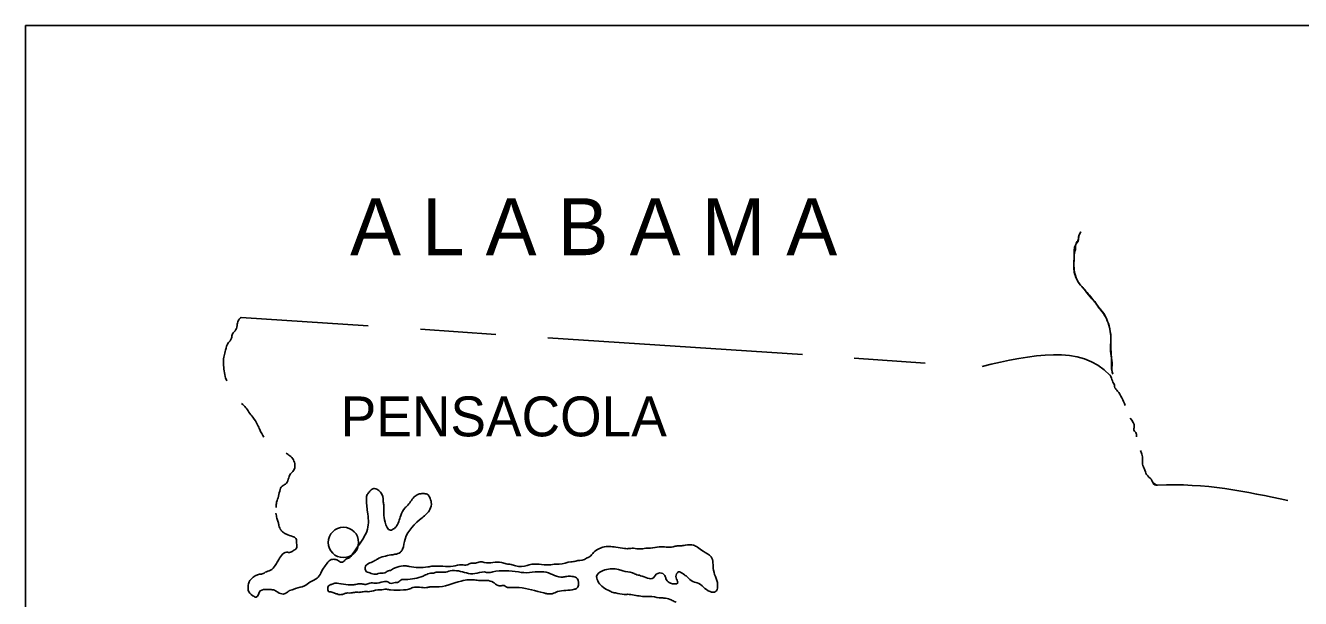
# Model space of a CAD drawing. Extents: x 315926 to 491925, y 1158891 to 1294891.
# Drawn here: x 435411 to 448942, y 1280810 to 1286891 of the extents above; entities that cross this region are included whole.
import ezdxf

# ---------------------------------------------------------------- set-up
doc = ezdxf.new("R2010")
doc.units = 0
doc.layers.add('V-ANNO-SYMB', color=7, linetype='Continuous')

msp = doc.modelspace()

# ---------------------------------------------------------------- linework, layer by layer
at = {"layer": 'V-ANNO-SYMB'}
for p, q in [((474924.24152864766, 1286890.60258966), (435411.05736746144, 1286890.5877054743)), ((435411.0573680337, 1286890.5877054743), (435411.0573726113, 1251238.69202066)), ((439048.86632875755, 1283701.8936220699), (437699.54312891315, 1283792.332821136)), ((440403.2367284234, 1283611.4328222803), (439602.3375285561, 1283666.570421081)), ((443655.95192865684, 1283399.299222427), (440953.12232889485, 1283576.044822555)), ((444958.84952825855, 1283307.4056223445), (444206.2263289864, 1283361.981621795))]:
    msp.add_line(p, q, dxfattribs=at)
msp.add_circle((438785.0007281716, 1281404.568021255), 160.9968943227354, dxfattribs=at)
msp.add_arc((447465.82008299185, 1282126.484151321), 121.89745971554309, 213.18290550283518, 248.6293777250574, dxfattribs=at)
for points in [[(446948.72072920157, 1283194.1496222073), (446937.812727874, 1283248.7328222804), (446937.812727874, 1283344.2408224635), (446929.6335290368, 1283453.3928225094), (446929.6335284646, 1283578.917622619), (446910.5607284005, 1283703.5424215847), (446875.10792879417, 1283793.6000231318), (446823.29672865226, 1283870.006421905), (446749.66952871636, 1283968.2432222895), (446651.5047282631, 1284085.5816217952), (446575.14872812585, 1284181.0896219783), (446537.0895286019, 1284303.2952234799), (446539.8183288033, 1284450.650422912), (446553.4551286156, 1284559.802422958), (446586.1719285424, 1284617.1144220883), (446586.1719285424, 1284647.1312231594), (446613.445528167, 1284701.7072214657)], [(446949.9015283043, 1283190.1680223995), (446942.70152887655, 1283211.7680223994), (446942.7015283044, 1283308.9680223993), (446928.30152830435, 1283409.7680223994), (446928.30152830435, 1283596.968023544), (446913.90152887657, 1283686.9680223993), (446881.50152830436, 1283780.5680223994), (446823.90152887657, 1283874.1680223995), (446802.30152887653, 1283895.768021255), (446759.1015288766, 1283960.5680223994), (446708.70152887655, 1284010.9680223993), (446643.90152887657, 1284097.3680223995), (446597.1015288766, 1284147.7680223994), (446553.90152944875, 1284237.7680223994), (446539.50152830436, 1284316.9680223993), (446539.50152887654, 1284424.968023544), (446546.70152887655, 1284489.7680223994), (446553.9015283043, 1284514.9680223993), (446561.10152830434, 1284579.7680223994), (446582.70152773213, 1284615.7680223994), (446589.9015283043, 1284658.9680223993), (446611.5015277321, 1284702.1680223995)], [(437699.54312891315, 1283792.332821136), (437674.1055289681, 1283767.6728220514), (437658.3591287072, 1283720.4120211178), (437642.61992906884, 1283663.3088205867), (437609.161527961, 1283618.0136202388), (437597.36072840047, 1283572.7256205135), (437581.6143281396, 1283543.1840204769), (437565.8751285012, 1283527.4304201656), (437534.3895286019, 1283444.7240213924), (437518.64312834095, 1283385.6480219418), (437510.7735288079, 1283322.6336206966), (437516.6775283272, 1283243.865621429), (437530.4511285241, 1283167.0632204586), (437538.32072862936, 1283139.494420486), (437548.1631287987, 1283119.802420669)], [(447081.8271291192, 1282858.809622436), (447000.0207286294, 1283011.6224234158), (446983.65512918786, 1283030.7240213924), (446972.7471284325, 1283047.0968226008), (446967.29672865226, 1283074.39202066), (446945.48072885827, 1283118.0528215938), (446920.93592886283, 1283178.0864225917), (446918.52392858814, 1283180.7360228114), (445562.1231284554, 1283273.2200235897)], [(437703.56792787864, 1282879.09202066), (437750.799928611, 1282833.8040209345), (437780.312727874, 1282788.5088205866), (437823.60632910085, 1282733.3712206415), (437874.76952871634, 1282652.637620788), (437896.4199290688, 1282601.4384226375), (437941.67912916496, 1282520.6976221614)], [(447201.6783290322, 1282526.7528227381), (447198.9495282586, 1282562.2272219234), (447174.4119294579, 1282594.9800226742), (447177.1335284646, 1282630.4544230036), (447133.5087294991, 1282723.2336229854)], [(438177.39992861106, 1282352.109622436), (438216.75512861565, 1282324.5408213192), (438254.1447291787, 1282281.2184221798), (438269.8911288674, 1282226.0808210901), (438256.1175286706, 1282167.0048227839), (438224.63192877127, 1282133.524820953), (438169.53032907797, 1282023.2496210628), (438136.0791291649, 1282003.557621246), (438108.5319293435, 1281950.3856207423), (438090.8199284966, 1281877.5288210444), (438073.10792936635, 1281818.4528215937), (438071.1423282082, 1281777.0960207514)], [(448806.7599288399, 1281848.7504217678), (447425.08712877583, 1282012.2552225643), (447395.084729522, 1282014.9840227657), (447365.0895286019, 1282061.3736227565), (447321.46472906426, 1282110.4920229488), (447299.6487292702, 1282140.5088217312), (447291.46232809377, 1282170.5256228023), (447269.6535283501, 1282219.64402185), (447266.9247287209, 1282282.4064241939), (447258.7455293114, 1282342.4400217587), (447242.3799287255, 1282380.6432222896)], [(438068.70152887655, 1281714.1680223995), (438079.50152887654, 1281663.768021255), (438093.9015283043, 1281620.5680223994), (438101.1015288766, 1281584.5680201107), (438122.7015283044, 1281534.1680223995), (438144.30152944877, 1281512.568021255), (438180.30152944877, 1281490.9680223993), (438245.10153002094, 1281469.3680212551), (438281.10152944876, 1281447.7680223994), (438288.30152887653, 1281397.3680212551), (438288.30152887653, 1281343.3680212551), (438259.50152887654, 1281321.7680201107), (438223.50152830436, 1281300.168021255), (438180.30152887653, 1281300.1680201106), (438090.30152887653, 1281206.5680223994), (438061.50152887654, 1281159.7680223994), (438011.10152944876, 1281109.3680223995), (437953.50152887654, 1281087.7680201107), (437931.90152887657, 1281073.3680212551), (437895.90152887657, 1281066.1680201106), (437809.50153002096, 1281019.3680201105), (437780.70152887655, 1280976.1680223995), (437773.50152887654, 1280925.7680223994), (437773.50152887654, 1280896.9680201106), (437823.90152944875, 1280839.3680201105), (437859.90152944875, 1280824.968021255), (437903.10153002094, 1280889.7680201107), (437975.1015288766, 1280904.1680201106), (438003.90152887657, 1280904.1680201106), (438054.30152887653, 1280896.9680223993), (438090.30152887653, 1280875.3680212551), (438147.90152887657, 1280857.3680212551), (438183.90152887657, 1280871.7680223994), (438212.70152887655, 1280893.3680201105), (438241.50152887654, 1280900.5680223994), (438277.50152887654, 1280914.968021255), (438371.10152944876, 1280943.768021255), (438428.70152887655, 1280983.3680201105), (438507.90152944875, 1281026.5680201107), (438543.90152887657, 1281076.968021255), (438565.5015294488, 1281120.1680201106), (438601.5015294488, 1281170.568021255), (438644.70152887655, 1281217.3680201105), (438695.1015288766, 1281224.568021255), (438731.1015288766, 1281210.1680223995), (438752.70152887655, 1281195.7680223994), (438795.90152944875, 1281210.1680223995), (438817.50152887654, 1281231.768021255), (438839.1015288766, 1281238.9680223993), (438882.30152944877, 1281282.1680223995), (438997.50152887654, 1281451.3680212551), (439040.70152944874, 1281544.968021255), (439040.70152887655, 1281728.568021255), (439029.90152944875, 1281872.5680223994), (439037.10152830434, 1281912.1680201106), (439065.90152887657, 1281948.168021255), (439080.30152887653, 1281962.5680223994), (439116.30152944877, 1281976.9680223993), (439159.50152887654, 1281955.3680212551), (439206.30152830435, 1281868.9680201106), (439206.30152944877, 1281847.3680212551), (439213.50152887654, 1281804.168021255), (439213.50153002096, 1281714.168021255), (439227.90152887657, 1281620.5680223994), (439285.50152887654, 1281534.168021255), (439307.10152944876, 1281541.3680201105), (439343.1015288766, 1281570.1680223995), (439393.50152887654, 1281688.968021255), (439436.70152887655, 1281768.168021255), (439458.30152887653, 1281789.768021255), (439537.50152830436, 1281886.9680223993), (439580.70152887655, 1281915.768021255), (439631.1015288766, 1281922.968021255), (439674.30152830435, 1281915.768021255), (439710.30152830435, 1281858.168021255), (439717.5015294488, 1281829.3680223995), (439703.1015288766, 1281753.768021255), (439620.30152887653, 1281667.3680223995), (439440.30152944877, 1281440.568021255), (439411.5015294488, 1281332.568021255), (439389.90152887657, 1281300.168021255), (439332.30152944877, 1281278.5680201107), (439289.1015288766, 1281271.3680212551), (439145.10152944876, 1281228.168021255), (439109.10152944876, 1281206.5680223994), (439015.50152887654, 1281138.1680223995), (439022.70152944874, 1281102.168021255), (439065.90152944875, 1281080.5680223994), (439123.50152887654, 1281066.168021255), (439152.30152887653, 1281073.3680212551), (439224.30152887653, 1281080.568021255)], [(439224.30152887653, 1281080.568021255), (439253.1015288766, 1281098.5680223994), (439296.30152944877, 1281112.9680223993), (439317.90152887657, 1281127.3680212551), (439353.90152887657, 1281141.7680223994), (439440.30152887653, 1281156.1680223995), (439483.5015294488, 1281148.968021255), (439681.50152887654, 1281145.3680223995), (439731.90152944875, 1281152.5680223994), (439947.90152887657, 1281152.568021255), (440041.50152887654, 1281166.9680201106), (440099.1015288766, 1281166.9680223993), (440142.30152944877, 1281184.9680223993), (440185.5015294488, 1281184.9680223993), (440235.90152944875, 1281199.3680201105), (440279.10152830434, 1281192.1680223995), (440462.70152944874, 1281192.1680223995), (440513.10152830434, 1281177.7680223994), (440563.50152830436, 1281170.568021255), (440613.90152944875, 1281156.1680223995), (440736.30152944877, 1281159.7680223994), (440757.90152944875, 1281166.968021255), (440966.70152887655, 1281166.968021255), (441038.70152944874, 1281174.1680223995), (441074.70152944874, 1281174.1680201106), (441200.701530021, 1281199.3680223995), (441251.10152944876, 1281206.5680223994), (441272.70152887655, 1281213.7680223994), (441294.30152830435, 1281213.7680223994), (441387.90152887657, 1281249.7680223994), (441409.50152830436, 1281264.168021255), (441438.30152830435, 1281296.5680223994), (441488.70152887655, 1281332.5680223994), (441539.1015288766, 1281354.1680223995), (441675.90152887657, 1281354.1680223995), (441769.50152887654, 1281339.7680201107), (441819.90152887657, 1281339.7680223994), (441848.7015283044, 1281343.3680223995), (441913.50152830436, 1281336.168021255), (441949.50152887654, 1281336.168021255), (442007.10152944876, 1281343.3680223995), (442043.1015288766, 1281343.3680212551), (442136.70152887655, 1281357.7680223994), (442284.30152944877, 1281357.7680223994), (442327.50152830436, 1281368.5680223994), (442363.50152887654, 1281368.5680223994), (442413.90152887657, 1281375.7680223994), (442500.30152887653, 1281375.768021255), (442543.5015294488, 1281354.168021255), (442601.1015288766, 1281310.9680223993), (442687.50152887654, 1281253.3680223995), (442712.70152887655, 1281109.3680212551), (442755.90152887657, 1280932.968021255), (442734.30152944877, 1280882.5680223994), (442676.70152887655, 1280882.5680223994), (442539.90152887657, 1280976.1680223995), (442511.10152944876, 1280983.3680223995), (442446.30152887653, 1281026.5680223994), (442431.9015283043, 1281040.9680223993), (442392.30152887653, 1281069.768021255), (442341.90152887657, 1281091.3680223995), (442320.30152887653, 1281069.768021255), (442320.30152944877, 1281015.768021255), (442331.10152944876, 1280972.5680223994), (442302.30152944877, 1280965.3680223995), (442255.5015294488, 1280972.5680223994), (442212.30152887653, 1281008.568021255), (442205.1015288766, 1281030.1680223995), (442176.30152887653, 1281073.3680212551), (442104.30152944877, 1281066.168021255), (442075.5015294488, 1281030.1680223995), (441938.70152944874, 1281051.7680223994), (441888.30152830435, 1281066.1680223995), (441852.30152887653, 1281080.5680223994), (441751.50153002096, 1281102.1680223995), (441704.70152944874, 1281116.5680223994), (441560.70152944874, 1281112.968021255), (441474.30152887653, 1281055.3680223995), (441528.30152887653, 1280940.1680223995), (441593.1015288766, 1280896.9680201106), (441621.901530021, 1280882.568021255), (441672.30152887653, 1280868.1680223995), (441765.90152944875, 1280853.7680223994), (441816.30152887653, 1280853.7680223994), (441960.30152944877, 1280832.1680223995), (442032.30152944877, 1280832.1680223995), (442136.70152887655, 1280817.7680223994), (442187.10152944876, 1280814.1680223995), (442251.90152887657, 1280799.7680223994), (442295.10152944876, 1280778.1680223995), (442316.70152887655, 1280770.9680201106)], [(438734.70152887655, 1280968.9680201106), (438835.50152887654, 1280954.5680223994), (438885.90152944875, 1280954.568021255), (438929.1015288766, 1280961.7680201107), (438979.50152887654, 1280965.3680212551), (439022.70152887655, 1280958.168021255), (439065.90152944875, 1280972.568021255), (439123.5015294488, 1280972.5680223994), (439206.30152944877, 1280986.968021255), (439256.7015283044, 1280986.968021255), (439278.30152887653, 1280972.568021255), (439307.10152830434, 1280972.5680223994), (439335.90152887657, 1280979.7680223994), (439357.50152887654, 1280979.7680201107), (439393.50152887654, 1281004.9680201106), (439443.90152887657, 1281012.1680201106), (439631.10152944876, 1281048.1680223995), (439681.50152887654, 1281069.7680223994), (439710.30152887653, 1281076.9680223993), (439731.90152887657, 1281076.9680201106), (439767.90152887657, 1281087.7680223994), (439854.30152830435, 1281087.768021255), (439919.1015288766, 1281102.168021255), (440005.50152830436, 1281102.1680223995), (440178.30152944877, 1281073.3680223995), (440282.70152887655, 1281091.3680223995), (440325.90152887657, 1281084.1680223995), (440369.1015288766, 1281091.3680223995), (440642.70152887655, 1281091.3680212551), (440700.30152887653, 1281084.1680201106), (440937.90152944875, 1281087.7680223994), (441114.30152887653, 1281037.3680201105), (441157.50152887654, 1281044.5680223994), (441207.90152887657, 1281044.5680223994), (441258.30152887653, 1281030.1680223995), (441279.90152944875, 1280965.3680223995), (441265.50152887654, 1280922.1680223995), (441236.70152887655, 1280907.7680223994), (441056.70152944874, 1280882.5680223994), (440999.10152944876, 1280860.9680223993), (440948.70152944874, 1280860.968021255), (440912.70152944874, 1280868.1680223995), (440649.90152887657, 1280925.7680223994), (440570.70152887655, 1280925.7680223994), (440513.10152830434, 1280932.9680223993), (440491.50152887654, 1280947.3680223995), (440448.30152830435, 1280943.768021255), (440405.10152944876, 1280958.1680223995), (440376.30152887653, 1280979.7680223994), (440304.30152944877, 1281001.3680223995), (440217.9015283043, 1281001.3680223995), (440160.30152887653, 1281008.5680223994), (440117.1015288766, 1281008.5680223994), (440034.30152887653, 1280994.1680223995), (439767.90152887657, 1280932.968021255), (439703.10152944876, 1280932.9680223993), (439667.1015288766, 1280925.768021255), (439523.10152944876, 1280925.7680201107), (439479.90152887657, 1280907.768021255), (439422.30152944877, 1280900.5680223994), (439285.50152887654, 1280900.568021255), (439242.30152887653, 1280907.768021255), (439177.50152887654, 1280900.5680223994), (439148.70152944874, 1280900.568021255), (439062.30152944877, 1280882.568021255), (439008.30152887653, 1280882.5680201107), (438957.90152944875, 1280875.3680201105), (438914.70152944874, 1280875.3680223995), (438864.30152944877, 1280868.1680201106), (438828.30152944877, 1280868.1680201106)], [(438648.30152887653, 1280958.168021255), (438644.70152944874, 1280954.5680201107), (438626.7015283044, 1280943.768021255), (438619.50152887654, 1280925.7680201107), (438619.5015294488, 1280900.5680223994), (438626.70152887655, 1280882.5680223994), (438651.90152944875, 1280878.968021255), (438691.5015294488, 1280864.5680223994), (438709.5015294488, 1280860.9680201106), (438727.5015294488, 1280853.7680201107), (438774.30152944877, 1280853.7680201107), (438792.30152887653, 1280860.9680223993), (438828.30152944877, 1280868.1680201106)], [(438648.30152887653, 1280958.168021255), (438666.30152887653, 1280961.768021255), (438684.30152944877, 1280968.9680223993), (438702.30152887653, 1280972.568021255), (438734.70152887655, 1280968.9680201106)]]:
    msp.add_spline(points, degree=3, dxfattribs=at)

# ---------------------------------------------------------------- texts
for s, height, p in [('A L A B A M A', 604.7999999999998, (438856.0491021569, 1284453.0034037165)), ('PENSACOLA', 423.35999999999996, (438756.27745279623, 1282530.516856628))]:
    msp.add_text(s, height=height, rotation=8.564476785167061e-09, dxfattribs=at).set_placement(p)

doc.saveas('drawing.dxf')
